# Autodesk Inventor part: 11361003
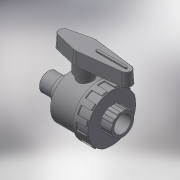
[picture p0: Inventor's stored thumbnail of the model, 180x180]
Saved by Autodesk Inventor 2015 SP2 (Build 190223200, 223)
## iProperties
Created: 2017-11
Part Number: 11361003
Material: Generic
Description: PLASSON ONE NUT VALVE MALE-FEMALE ADAPTOR 3/8" PVC
Document SubType Name: Modeling
Designer: KIM
Density: 1 g/cm^3
Appearance: Default
Author: KIM
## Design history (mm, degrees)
derived "113610.ipt"
feature "Solid1::113610.ipt"
tag "TaggingFeature1"
body "Solid1"
other parameters: "d0" = 67, "d2" = 45, "d4" = 11.96, "d8" = 40.5, "d13" = 0.4485, "d25" = 0.299, "d26" = 0.4485, "d29" = 9, "d30" = 0, "d35" = 0.4485, "d39" = 22.5, "d45" = 360 deg, "d47" = 0.299, "d50" = 24.75, "d51" = 13.5, "d53" = 0, "d58" = 0, "d59" = 0.4485, "d63" = 18, "d64" = 45, "d66" = 65, "d68" = 9, "d69" = 19.5, "d70" = 11.25, "d71" = 3 deg, "d73" = 0.9, "d74" = 26, "d75" = 1.35, "d76" = 0, "d77" = 0.299, "d78" = 14.95, "d79" = 12, "d80" = 45, "d81" = 12.6, "d82" = 43.2, "d83" = 9.6, "d84" = 20.93, "d85" = 11.6634, "d87" = 120 deg, "d90" = 360 deg, "d92" = 6.75, "d95" = 3.375, "d96" = 16.662, "d97" = 14.4, "d98" = 12, "d99" = 15 deg, "d100" = 19.9944, "d101" = 2.99, "d102" = 1.495, "G_" = 14.95, "l_" = 12, "H_" = 67, "K_" = 45, "F_" = 45, "J_" = 65, "R_" = 16.662, "d67" = 18, "d72" = 4.5
